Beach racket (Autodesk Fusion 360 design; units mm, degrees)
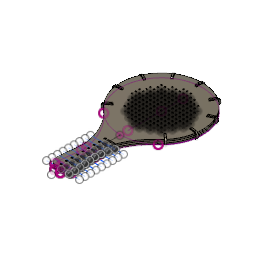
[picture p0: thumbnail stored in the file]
sketch "Sketch1" plane through (0, 0, 0) normal (0, 1, 0) x axis (1, 0, 0)
  line L1 (0, 225) -> (0, 0)
  line L2 (-7.5, -169.8262) -> (7.5, -169.8262)
  line L3 (17.5, 147.5392) -> (-17.5, 147.5392)
  line L4 (17.5, -73.5003) -> (17.5, 147.5392)
  line L5 (-17.5, 147.5392) -> (17.5, -169.8262)
  line L6 (17.5, 147.5392) -> (-17.5, -169.8262)
  line L7 (-17.5, 147.5392) -> (-17.5, -87.4536)
  curve K1 (17.5, -73.5003) -> (22.5, -154.8262)
  curve K2 (-17.5, -73.5003) -> (-22.5, -154.8262)
  curve K3 (74.4422, 30.1713) -> (17.5, -87.4536)
  curve K4 (-74.4422, 30.1713) -> (-17.5, -87.4536)
  arc A1 centre (-7.5, -154.8262) radius 15 clockwise from (-7.5, -169.8262) to (-22.5, -154.8262)
  arc A2 centre (7.5, -154.8262) radius 15 clockwise from (22.5, -154.8262) to (7.5, -169.8262)
  circle C1 centre (0, 113.3638) radius 111.6362
  point P4 (17.5, -169.8262)
  point P5 (-17.5, -169.8262)
  point P7 (17.5, 147.5392)
  dimension "d2" distance P4 P5 = 35
  dimension "d3" distance P4 P7 = 317.3653
  dimension "d5" radius A1 = 15
  dimension "d6" radius A2 = 15
extrude "Extrude2" new body sketch "Sketch1" profile of L1 L2 L7 L3 L4 A1 A2 K1 K2 C1 K3 K4 blind 4 from offset 8
extrude "Extrude1" new body sketch "Sketch1" profile of L1 L2 L7 L3 L4 A1 A2 K1 K2 C1 K3 K4 along normal blind 4
sketch "Sketch3" plane through (0, 0, 0) normal (0, 1, 0) x axis (1, 0, 0)
  line L1 (-2, 214.9793) -> (2, 214.9793)
  line L2 (-2, 224.9808) -> (-2, 214.9793)
  line L3 (2, 214.9793) -> (2, 224.9793)
  line L4 (-2, 206.9793) -> (2, 206.9793)
  line L5 (-2, 210.9793) -> (-2, 206.9793)
  line L6 (2, 210.9793) -> (-2, 210.9793)
  line L7 (2, 206.9793) -> (2, 210.9793)
  line L8 (-2, 210.9793) -> (2, 206.9793)
  line L9 (2, 210.9793) -> (-2, 206.9793)
  line L10 (0, 213) -> (0, 207.805)
  line L11 (0, 21.7014) -> (0, 171.8058)
  line L12 (-2, 225.6306) -> (-2, 224.9808)
  line L13 (2, 225.6306) -> (-2, 225.6306)
  line L14 (2, 224.9793) -> (2, 225.6306)
  line L15 (120, 80.3312) -> (0, 80.3312)
  line L16 (1, 225.6306) -> (2, 225.6306)
  line L17 (1, 221) -> (1, 225.6306)
  line L18 (2, 221) -> (1, 221)
  line L19 (2, 225.6306) -> (2, 221)
  line L20 (-1, 225.6306) -> (-2, 225.6306)
  line L21 (-1, 221) -> (-1, 225.6306)
  line L22 (-2, 221) -> (-1, 221)
  line L23 (-2, 225.6306) -> (-2, 221)
  curve K1 (74.4422, 30.1713) -> (17.5, -87.4536)
  curve K2 (-74.4422, 30.1713) -> (-17.5, -87.4536)
  curve K3 (-17.5, -73.5003) -> (-22.5, -154.8262)
  curve K4 (17.5, -73.5003) -> (22.5, -154.8262)
  line L24 (17.5, 147.5392) -> (-17.5, -169.8262)
  line L25 (-7.5, -169.8262) -> (7.5, -169.8262)
  line L26 (-56.51, 204.9944) -> (-57.3513, 204.4538)
  line L27 (-54.4574, 194.4019) -> (-48.9298, 193.1994)
  line L28 (-51.0924, 196.5644) -> (-54.4574, 194.4019)
  line L29 (-51.0924, 196.5644) -> (-52.2948, 191.0369)
  line L30 (-59.0135, 208.8899) -> (-62.3785, 206.7274)
  line L31 (-53.2549, 199.9294) -> (-58.6613, 208.342)
  line L32 (-62.0272, 206.1807) -> (-56.62, 197.7669)
  line L33 (-53.8674, 197.1831) -> (-51.0587, 192.8128)
  line L34 (-58.6613, 208.342) -> (-59.0135, 208.8899)
  line L35 (-52.2948, 191.0369) -> (-48.9298, 193.1994)
  line L36 (-62.3785, 206.7274) -> (-62.0272, 206.1807)
  line L37 (-59.8548, 208.3493) -> (-59.0135, 208.8899)
  line L38 (-57.3513, 204.4538) -> (-59.8548, 208.3493)
  line L39 (-54.4574, 194.4019) -> (-52.2948, 191.0369)
  line L40 (-56.62, 197.7669) -> (-53.2549, 199.9294)
  line L41 (-59.0135, 208.8899) -> (-56.51, 204.9944)
  line L42 (-61.5373, 207.268) -> (-62.3785, 206.7274)
  line L43 (-59.875, 202.8319) -> (-59.0338, 203.3725)
  line L44 (-59.0338, 203.3725) -> (-61.5373, 207.268)
  line L45 (-62.3785, 206.7274) -> (-59.875, 202.8319)
  line L46 (-48.9298, 193.1994) -> (-51.0924, 196.5644)
  line L47 (-97.0785, 159.8968) -> (-97.4939, 158.9871)
  line L48 (-89.6249, 152.0955) -> (-84.3248, 154.0723)
  line L49 (-87.9633, 155.734) -> (-89.6249, 152.0955)
  line L50 (-87.9633, 155.734) -> (-85.9864, 150.4338)
  line L51 (-101.2906, 161.8204) -> (-102.9523, 158.1819)
  line L52 (-91.6018, 157.3957) -> (-100.6981, 161.5498)
  line L53 (-102.3612, 157.9119) -> (-93.2635, 153.7571)
  line L54 (-90.6323, 154.7542) -> (-85.9067, 152.5961)
  line L55 (-100.6981, 161.5498) -> (-101.2906, 161.8204)
  line L56 (-85.9864, 150.4338) -> (-84.3248, 154.0723)
  line L57 (-102.9523, 158.1819) -> (-102.3612, 157.9119)
  line L58 (-101.7061, 160.9108) -> (-101.2906, 161.8204)
  line L59 (-97.4939, 158.9871) -> (-101.7061, 160.9108)
  line L60 (-89.6249, 152.0955) -> (-85.9864, 150.4338)
  line L61 (-93.2635, 153.7571) -> (-91.6018, 157.3957)
  line L62 (-101.2906, 161.8204) -> (-97.0785, 159.8968)
  line L63 (-102.5369, 159.0915) -> (-102.9523, 158.1819)
  line L64 (-98.7402, 156.2582) -> (-98.3247, 157.1679)
  line L65 (-98.3247, 157.1679) -> (-102.5369, 159.0915)
  line L66 (-102.9523, 158.1819) -> (-98.7402, 156.2582)
  line L67 (-84.3248, 154.0723) -> (-87.9633, 155.734)
  line L68 (-106.8252, 100.0252) -> (-106.6829, 99.0354)
  line L69 (-96.3372, 97.4921) -> (-92.9472, 102.0206)
  line L70 (-96.9065, 101.4513) -> (-96.3372, 97.4921)
  line L71 (-96.9065, 101.4513) -> (-92.3779, 98.0613)
  line L72 (-111.4087, 99.3662) -> (-110.8395, 95.4069)
  line L73 (-100.8658, 100.8821) -> (-110.764, 99.4589)
  line L74 (-110.1963, 95.4994) -> (-100.2965, 96.9228)
  line L75 (-98.622, 99.1841) -> (-93.4799, 99.9234)
  line L76 (-110.764, 99.4589) -> (-111.4087, 99.3662)
  line L77 (-92.3779, 98.0613) -> (-92.9472, 102.0206)
  line L78 (-110.8395, 95.4069) -> (-110.1963, 95.4994)
  line L79 (-111.2664, 98.3764) -> (-111.4087, 99.3662)
  line L80 (-106.6829, 99.0354) -> (-111.2664, 98.3764)
  line L81 (-96.3372, 97.4921) -> (-92.3779, 98.0613)
  line L82 (-100.2965, 96.9228) -> (-100.8658, 100.8821)
  line L83 (-111.4087, 99.3662) -> (-106.8252, 100.0252)
  line L84 (-110.9818, 96.3968) -> (-110.8395, 95.4069)
  line L85 (-106.256, 96.0659) -> (-106.3983, 97.0558)
  line L86 (-106.3983, 97.0558) -> (-110.9818, 96.3968)
  line L87 (-110.8395, 95.4069) -> (-106.256, 96.0659)
  line L88 (-92.9472, 102.0206) -> (-96.9065, 101.4513)
  line L89 (-82.6557, 44.3886) -> (-82.0009, 43.6329)
  line L90 (-72.4631, 47.9278) -> (-72.0595, 53.5703)
  line L91 (-75.0825, 50.9508) -> (-72.4631, 47.9278)
  line L92 (-75.0825, 50.9508) -> (-69.4401, 50.5473)
  line L93 (-86.1553, 41.3562) -> (-83.5359, 38.3332)
  line L94 (-78.1055, 48.3314) -> (-85.663, 41.7828)
  line L95 (-83.0448, 38.7587) -> (-75.4861, 45.3084)
  line L96 (-75.3, 48.116) -> (-71.3739, 51.518)
  line L97 (-85.663, 41.7828) -> (-86.1553, 41.3562)
  line L98 (-69.4401, 50.5473) -> (-72.0595, 53.5703)
  line L99 (-83.5359, 38.3332) -> (-83.0448, 38.7587)
  line L100 (-85.5004, 40.6005) -> (-86.1553, 41.3562)
  line L101 (-82.0009, 43.6329) -> (-85.5004, 40.6005)
  line L102 (-72.4631, 47.9278) -> (-69.4401, 50.5473)
  line L103 (-75.4861, 45.3084) -> (-78.1055, 48.3314)
  line L104 (-86.1553, 41.3562) -> (-82.6557, 44.3886)
  line L105 (-84.1907, 39.089) -> (-83.5359, 38.3332)
  line L106 (-80.0363, 41.3656) -> (-80.6911, 42.1214)
  line L107 (-80.6911, 42.1214) -> (-84.1907, 39.089)
  line L108 (-83.5359, 38.3332) -> (-80.0363, 41.3656)
  line L109 (-72.0595, 53.5703) -> (-75.0825, 50.9508)
  line L110 (-32.2436, 10.6511) -> (-31.2841, 10.3694)
  line L111 (-25.5825, 19.139) -> (-28.2935, 24.1039)
  line L112 (-29.4204, 20.266) -> (-25.5825, 19.139)
  line L113 (-29.4204, 20.266) -> (-24.4555, 22.977)
  line L114 (-33.5482, 6.2081) -> (-29.7102, 5.0812)
  line L115 (-30.5474, 16.428) -> (-33.3647, 6.8331)
  line L116 (-29.5271, 5.7046) -> (-26.7094, 15.3011)
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  point P9 (-2, 210.9793)
  point P10 (2, 210.9793)
  point P8 (-2, 206.9793)
  point P4 (2, 214.9793)
  point P16 (2, 224.9793)
  point P19 (2, 225.6306)
  point P22 (1, 225.6306)
  point P24 (2, 221)
  point P240 (0, 225)
  dimension "d37" distance P9 P10 = 4
  dimension "d38" distance P8 P9 = 4
  dimension "d39" distance P4 P10 = 4
  dimension "d40" distance P4 P16 = 10
  dimension "d47" distance P19 P22 = 1
  dimension "d64" distance P24 P240 = 4
  dimension "d54" C-Pattern1-Angle = 360
extrude "Extrude7" new body sketch "Sketch3" along normal blind 15 and against normal blind 5
extrude "Extrude6" cut sketch "Sketch3" along normal blind 15 and against normal blind 5
sketch "Sketch4" plane through (0, 0, 0) normal (1, 0, 0) x axis (0, 0, -1)
  line L1 (209.4993, 14.9981) -> (222, 14.9981)
  line L2 (217, 12) -> (217, 8)
  line L3 (217, 3.9985) -> (217, -0.0015)
  line L4 (209.4993, -2.9981) -> (222, -2.9981)
  line L5 (211, 11) -> (211, 12)
  line L6 (207, 11) -> (211, 11)
  line L7 (207, 12) -> (207, 11)
  line L8 (211, 9) -> (211, 8)
  line L9 (207, 9) -> (211, 9)
  line L10 (207, 8) -> (207, 9)
  line L11 (211, 2.9985) -> (211, 3.9985)
  line L12 (207, 2.9985) -> (211, 2.9985)
  line L13 (207, 3.9985) -> (207, 2.9985)
  line L14 (211, 1) -> (211, 0)
  line L15 (207, 1) -> (211, 1)
  line L16 (207, 0) -> (207, 1)
  line L17 (225, 12) -> (221, 12)
  line L18 (225, 8) -> (225, 12)
  line L19 (221, 8) -> (225, 8)
  line L20 (221, 12) -> (221, 8)
  line L21 (224.9808, 4) -> (221, 4)
  line L22 (224.9808, 0) -> (224.9808, 4)
  line L23 (221, 0) -> (224.9808, 0)
  line L24 (221, 4) -> (221, 0)
  line L25 (215, 12) -> (211, 12)
  line L26 (215, 8) -> (215, 12)
  line L27 (211, 8) -> (215, 8)
  line L28 (215, 3.9985) -> (211, 3.9985)
  line L29 (215, 0) -> (215, 3.9985)
  line L30 (211, 0) -> (215, 0)
  line L31 (211, 1) -> (211, 0)
  line L32 (211, 3.9985) -> (211, 2.9985)
  line L33 (211, 9) -> (211, 8)
  line L34 (211, 12) -> (211, 11)
  line L35 (221, 12) -> (225, 12)
  line L36 (211, 12) -> (215, 12)
  line L37 (207, 12) -> (217, 10)
  line L38 (215, 8) -> (211, 8)
  line L39 (225, 8) -> (221, 8)
  line L40 (206.9793, 3.9969) -> (217, 1.9985)
  line L41 (224.9808, 0) -> (221, 0)
  line L42 (221, 3.9969) -> (222, 3.9969)
  line L43 (222, 4) -> (222, 3.9969)
  line L44 (206.9993, 3.9929) -> (206.9993, 3.9969)
  line L45 (206.9993, -0.4981) -> (206.9993, 0.004)
  line L46 (207, 11) -> (207, 12)
  line L47 (207, 8) -> (207, 9)
  line L48 (207, 12) -> (206.9993, 12.4981)
  line L49 (207, 3.9985) -> (207, 8)
  line L50 (211, 3.9969) -> (215, 3.9969)
  line L51 (206.9793, 3.9969) -> (207, 3.9969)
  line L52 (207, 0) -> (206.9793, 0)
  line L53 (215, 0) -> (211, 0)
  line L54 (207, 0.0041) -> (206.9793, 0)
  line L55 (217, 1.9985) -> (211, 0.8019)
  line L56 (211, 8.8) -> (207, 8)
  line L57 (217, 10) -> (215, 9.6)
  line L58 (41.0164, 0) -> (96.4872, 0)
  line L59 (98.4668, 0) -> (158.8277, 0)
  line L60 (113.3638, 100) -> (113.3638, 0)
  arc A1 centre (209.4993, 12.4981) radius 2.5 clockwise from (206.9993, 12.4981) to (209.4993, 14.9981)
  arc A2 centre (209.4993, -0.4981) radius 2.5 clockwise from (209.4993, -2.9981) to (206.9993, -0.4981)
  arc A3 centre (221.8146, 6) radius 9 clockwise from (221.6292, 14.9981) to (221.6292, -2.9981)
  arc A4 centre (221.8146, 6) radius 9 clockwise from (213.0403, 3.9969) to (213.04, 3.9985)
  point P9 (207, 12)
  point P29 (207, 11)
  point P8 (207, 8)
  point P32 (207, 9)
  point P33 (207, 3.9985)
  point P36 (207, 2.9985)
  point P38 (207, 0)
  point P41 (207, 1)
  point P27 (211, 12)
  point P54 (215, 12)
  point P34 (211, 3.9985)
  point P57 (215, 3.9985)
  point P28 (211, 11)
  point P35 (211, 2.9985)
  dimension "d65" radius A1 = 2.5
  dimension "d66" radius A2 = 2.5
  dimension "d67" distance P9 P29 = 1
  dimension "d68" distance P8 P32 = 1
  dimension "d69" distance P33 P36 = 1
  dimension "d70" distance P38 P41 = 1
  dimension "d71" distance P27 P54 = 4
  dimension "d72" distance P34 P57 = 4
  dimension "d77" distance P28 P29 = 4
  dimension "d78" distance P35 P36 = 4
extrude "Extrude8" new body sketch "Sketch4" profile of A4 L1 L45 L39 L36 L47 L2 L53 L51 L3 L4 A1 A2 L5 L6 L7 L8 L9 L10 L11 L12 L13 L14 L15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 along normal blind 2 and against normal blind 2
chamfer "Chamfer3" distance 1
circular_pattern "C-Pattern1" countU 11 TotalAngle 360
chamfer "Chamfer4" distance 1.5
chamfer "Chamfer5" distance 1.5
sketch "Sketch5" plane through (0, 0, 0) normal (0, 1, 0) x axis (1, 0, 0)
  curve K1 (-74.4422, 30.1713) -> (-17.5, -87.4536)
  curve K2 (74.4422, 30.1713) -> (17.5, -87.4536)
  curve K3 (-17.5, -73.5003) -> (-22.5, -154.8262)
  curve K4 (17.5, -73.5003) -> (22.5, -154.8262)
  line L1 (-7.5, -169.8262) -> (7.5, -169.8262)
  line L2 (0, 21.7014) -> (0, 171.8058)
  line L3 (50, -40) -> (-40, -40)
  line L4 (50, -55) -> (-40, -55)
  line L5 (50, -70) -> (-40, -70)
  line L6 (50, -85) -> (-40, -85)
  line L7 (50, -100) -> (-40, -100)
  line L8 (50, -115) -> (-40, -115)
  line L9 (50, -130) -> (-40, -130)
  line L10 (50, -145) -> (-40, -145)
  line L11 (50, -160) -> (-40, -160)
  line L12 (0, -186.6399) -> (0, 0)
  line L13 (-2, -42) -> (2, -42)
  line L14 (-2, -38) -> (-2, -42)
  line L15 (2, -38) -> (-2, -38)
  line L16 (2, -42) -> (2, -38)
  line L17 (-2, -38) -> (2, -42)
  line L18 (2, -38) -> (-2, -42)
  line L19 (-2, -53) -> (2, -53)
  line L20 (-2, -57) -> (-2, -53)
  line L21 (2, -57) -> (-2, -57)
  line L22 (2, -53) -> (2, -57)
  line L23 (-2, -57) -> (2, -53)
  line L24 (2, -57) -> (-2, -53)
  line L25 (-2, -72) -> (2, -72)
  line L26 (-2, -68) -> (-2, -72)
  line L27 (2, -68) -> (-2, -68)
  line L28 (2, -72) -> (2, -68)
  line L29 (-2, -68) -> (2, -72)
  line L30 (2, -68) -> (-2, -72)
  line L31 (-2, -87) -> (2, -87)
  line L32 (-2, -83) -> (-2, -87)
  line L33 (2, -83) -> (-2, -83)
  line L34 (2, -87) -> (2, -83)
  line L35 (-2, -83) -> (2, -87)
  line L36 (2, -83) -> (-2, -87)
  line L37 (-2, -102) -> (2, -102)
  line L38 (-2, -98) -> (-2, -102)
  line L39 (2, -98) -> (-2, -98)
  line L40 (2, -102) -> (2, -98)
  line L41 (-2, -98) -> (2, -102)
  line L42 (2, -98) -> (-2, -102)
  line L43 (-2, -117) -> (2, -117)
  line L44 (-2, -113) -> (-2, -117)
  line L45 (2, -113) -> (-2, -113)
  line L46 (2, -117) -> (2, -113)
  line L47 (-2, -113) -> (2, -117)
  line L48 (2, -113) -> (-2, -117)
  line L49 (-2, -132) -> (2, -132)
  line L50 (-2, -128) -> (-2, -132)
  line L51 (2, -128) -> (-2, -128)
  line L52 (2, -132) -> (2, -128)
  line L53 (-2, -128) -> (2, -132)
  line L54 (2, -128) -> (-2, -132)
  line L55 (-2, -147) -> (2, -147)
  line L56 (-2, -143) -> (-2, -147)
  line L57 (2, -143) -> (-2, -143)
  line L58 (2, -147) -> (2, -143)
  line L59 (-2, -143) -> (2, -147)
  line L60 (2, -143) -> (-2, -147)
  line L61 (-2, -162) -> (2, -162)
  line L62 (-2, -158) -> (-2, -162)
  line L63 (2, -158) -> (-2, -158)
  line L64 (2, -162) -> (2, -158)
  line L65 (-2, -158) -> (2, -162)
  line L66 (2, -158) -> (-2, -162)
  line L67 (21.5262, -52) -> (21.5262, -55)
  line L68 (18.3649, -67) -> (18.3649, -70)
  line L69 (17.3916, -82) -> (17.3916, -85)
  line L70 (18.4105, -97) -> (18.4105, -100)
  line L71 (20, -112) -> (20, -115)
  line L72 (21.775, -127) -> (21.775, -130)
  line L73 (22.7997, -142) -> (22.7997, -145)
  line L74 (21.5795, -157) -> (21.5795, -160)
  line L75 (26.3797, -37) -> (26.3797, -40)
  line L76 (24.5262, -57) -> (18.5262, -57)
  line L77 (24.5262, -53) -> (24.5262, -57)
  line L78 (18.5262, -53) -> (24.5262, -53)
  line L79 (18.5262, -57) -> (18.5262, -53)
  line L80 (24.5262, -53) -> (18.5262, -57)
  line L81 (18.5262, -53) -> (24.5262, -57)
  line L82 (6, -57) -> (24.5262, -57)
  line L83 (6, -53) -> (6, -57)
  line L84 (24.5262, -53) -> (6, -53)
  line L85 (24.5262, -57) -> (24.5262, -53)
  line L86 (21.3649, -72) -> (15.3649, -72)
  line L87 (21.3649, -68) -> (21.3649, -72)
  line L88 (15.3649, -68) -> (21.3649, -68)
  line L89 (15.3649, -72) -> (15.3649, -68)
  line L90 (21.3649, -68) -> (15.3649, -72)
  line L91 (15.3649, -68) -> (21.3649, -72)
  line L92 (6, -72) -> (21.3649, -72)
  line L93 (6, -68) -> (6, -72)
  line L94 (21.3649, -68) -> (6, -68)
  line L95 (21.3649, -72) -> (21.3649, -68)
  line L96 (20.3916, -87) -> (14.3916, -87)
  line L97 (20.3916, -83) -> (20.3916, -87)
  line L98 (14.3916, -83) -> (20.3916, -83)
  line L99 (14.3916, -87) -> (14.3916, -83)
  line L100 (20.3916, -83) -> (14.3916, -87)
  line L101 (14.3916, -83) -> (20.3916, -87)
  line L102 (6, -87) -> (20.3916, -87)
  line L103 (6, -83) -> (6, -87)
  line L104 (20.3916, -83) -> (6, -83)
  line L105 (20.3916, -87) -> (20.3916, -83)
  line L106 (21.4105, -102) -> (15.4105, -102)
  line L107 (21.4105, -98) -> (21.4105, -102)
  line L108 (15.4105, -98) -> (21.4105, -98)
  line L109 (15.4105, -102) -> (15.4105, -98)
  line L110 (21.4105, -98) -> (15.4105, -102)
  line L111 (15.4105, -98) -> (21.4105, -102)
  line L112 (6, -102) -> (21.4105, -102)
  line L113 (6, -98) -> (6, -102)
  line L114 (21.4105, -98) -> (6, -98)
  line L115 (21.4105, -102) -> (21.4105, -98)
  line L116 (23, -117) -> (17, -117)
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  point P42 (-2, -42)
  point P43 (-2, -38)
  point P44 (2, -38)
  point P47 (-2, -53)
  point P48 (-2, -57)
  point P49 (2, -57)
  point P53 (-2, -68)
  point P54 (2, -68)
  point P52 (-2, -72)
  point P57 (-2, -87)
  point P58 (-2, -83)
  point P59 (2, -83)
  point P63 (-2, -98)
  point P64 (2, -98)
  point P62 (-2, -102)
  point P67 (-2, -117)
  point P68 (-2, -113)
  point P69 (2, -113)
  point P73 (-2, -128)
  point P74 (2, -128)
  point P72 (-2, -132)
  point P77 (-2, -147)
  point P78 (-2, -143)
  point P79 (2, -143)
  point P83 (-2, -158)
  point P84 (2, -158)
  point P82 (-2, -162)
  point P250 (18.3649, -70)
  point P251 (18.3649, -67)
  point P252 (17.3916, -85)
  point P253 (17.3916, -82)
  point P254 (18.4105, -100)
  point P255 (18.4105, -97)
  point P256 (20, -115)
  point P257 (20, -112)
  point P258 (21.775, -130)
  point P259 (21.775, -127)
  point P260 (22.7997, -145)
  point P261 (22.7997, -142)
  point P262 (21.5795, -160)
  point P263 (21.5795, -157)
  point P264 (26.3797, -40)
  point P265 (26.3797, -37)
  point P268 (24.5262, -53)
  point P269 (18.5262, -53)
  point P276 (21.3649, -68)
  point P277 (15.3649, -68)
  point P284 (20.3916, -83)
  point P285 (14.3916, -83)
  point P292 (21.4105, -98)
  point P293 (15.4105, -98)
  point P300 (23, -113)
  point P301 (17, -113)
  point P308 (24.775, -128)
  point P309 (18.775, -128)
  point P316 (25.7997, -143)
  point P317 (19.7997, -143)
  point P324 (24.5795, -158)
  point P325 (18.5795, -158)
  point P332 (29.3797, -38)
  point P333 (23.3797, -38)
  point P340 (23.3797, -39)
  point P330 (23.3797, -42)
  point P343 (23.3797, -41)
  dimension "d90" distance P42 P43 = 4
  dimension "d91" distance P43 P44 = 4
  dimension "d92" distance P47 P48 = 4
  dimension "d93" distance P48 P49 = 4
  dimension "d94" distance P53 P54 = 4
  dimension "d95" distance P52 P53 = 4
  dimension "d96" distance P57 P58 = 4
  dimension "d97" distance P58 P59 = 4
  dimension "d98" distance P63 P64 = 4
  dimension "d99" distance P62 P63 = 4
  dimension "d100" distance P67 P68 = 4
  dimension "d101" distance P68 P69 = 4
  dimension "d102" distance P73 P74 = 4
  dimension "d103" distance P72 P73 = 4
  dimension "d104" distance P77 P78 = 4
  dimension "d105" distance P78 P79 = 4
  dimension "d106" distance P83 P84 = 4
  dimension "d107" distance P82 P83 = 4
  dimension "d109" diameter = 4
  dimension "d116" distance P250 P251 = 3
  dimension "d117" distance P252 P253 = 3
  dimension "d118" distance P254 P255 = 3
  dimension "d119" distance P256 P257 = 3
  dimension "d120" distance P258 P259 = 3
  dimension "d121" distance P260 P261 = 3
  dimension "d122" distance P262 P263 = 3
  dimension "d123" distance P264 P265 = 3
  dimension "d124" distance P268 P269 = 6
  dimension "d125" distance P276 P277 = 6
  dimension "d126" distance P284 P285 = 6
  dimension "d127" distance P292 P293 = 6
  dimension "d128" distance P300 P301 = 6
  dimension "d129" distance P308 P309 = 6
  dimension "d130" distance P316 P317 = 6
  dimension "d131" distance P324 P325 = 6
  dimension "d132" distance P332 P333 = 6
  dimension "d133" distance P333 P340 = 1
  dimension "d134" distance P330 P343 = 1
  dimension "d88" R-Pattern1-uDistance = 1
  dimension "d89" R-Pattern1-vDistance = -15
  dimension "d112" R-Pattern2-uDistance = 10
  dimension "d113" R-Pattern2-vDistance = 10
extrude "Extrude10" cut sketch "Sketch5" along normal blind 20
extrude "Extrude9" cut sketch "Sketch5" along normal blind 20
sketch "Sketch6" plane through (0, 0, 0) normal (1, 0, 0) x axis (0, 0, -1)
extrude "Extrude3" new body blind 2 second side blind 2
chamfer "Chamfer1" distance 1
